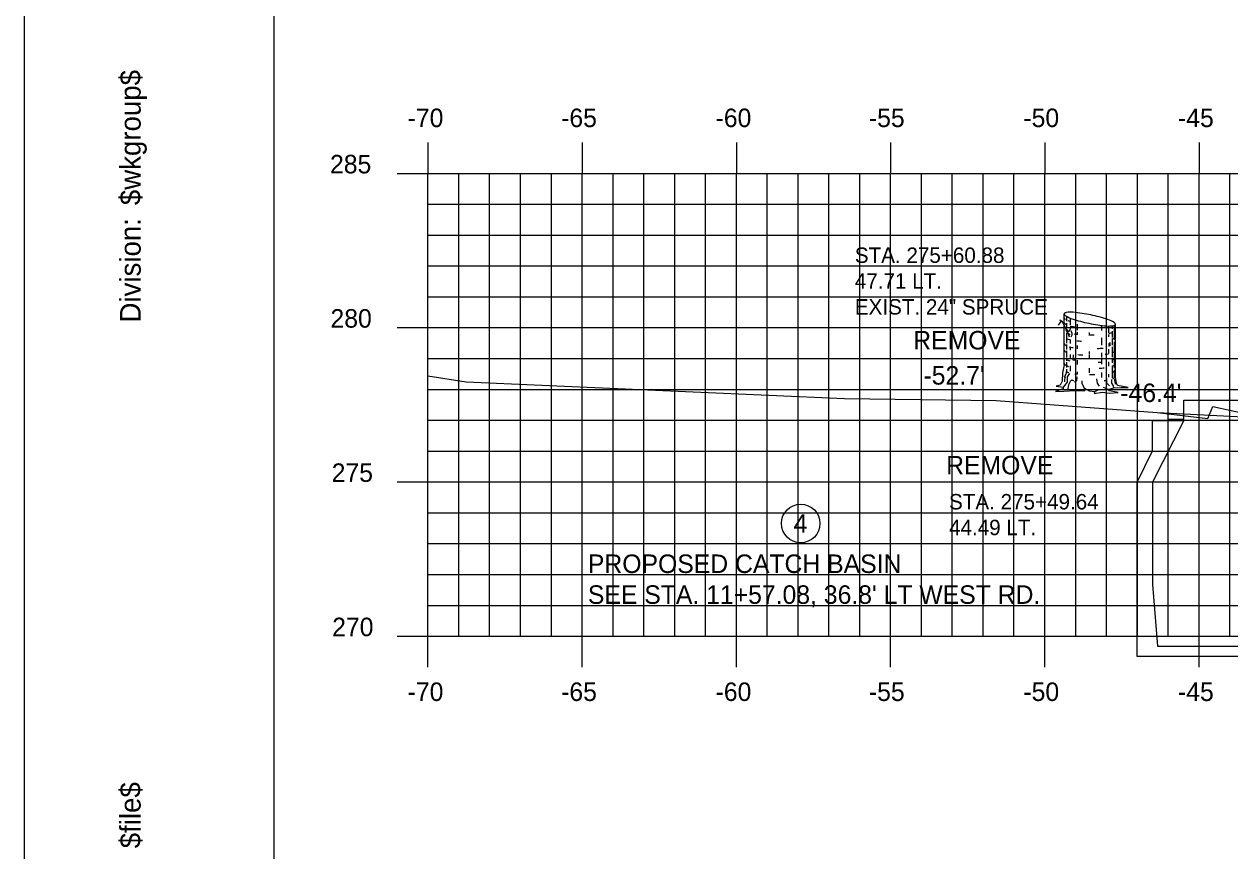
# Model space of a CAD drawing. Extents: x 853563 to 853733, y 366268 to 366378.
# Drawn here: x 853562.67 to 853601.77, y 366295.28 to 366322.07 of the extents above; entities that cross this region are included whole.
import ezdxf

# ---------------------------------------------------------------- set-up
doc = ezdxf.new("R2010")
doc.units = 0
for name, color, linetype in [('ANNOTATION', 7, 'Continuous'), ('BORDER', 7, 'Continuous'), ('D_Drainage_Text', 7, 'Continuous'), ('D_Roadway_FinishedGrade', 7, 'Continuous'), ('D_Text_Monospaced', 7, 'Continuous'), ('D_Text_Standard', 7, 'Continuous'), ('H_V ANNOTATION', 7, 'Continuous'), ('MAJOR', 7, 'Continuous'), ('MINOR', 7, 'Continuous'), ('PLOT BOUNDARY', 7, 'Continuous'), ('S_Drainage_CB', 7, 'Continuous'), ('S_Roadway_Centerline', 7, 'Continuous'), ('S_Trees_Conifer_Pay', 7, 'Continuous')]:
    doc.layers.add(name, color=color, linetype=linetype)

msp = doc.modelspace()

# ---------------------------------------------------------------- linework, layer by layer
at = {"layer": 'BORDER'}
msp.add_line((853570.768, 366376.236), (853570.768, 366271.236), dxfattribs=at)
at = {"layer": 'D_Drainage_Text'}
msp.add_circle((853587.853, 366305.89), 0.625, dxfattribs=at)
at = {"layer": 'D_Roadway_FinishedGrade'}
msp.add_line((853599.411, 366309.486), (853604.283, 366309.236), dxfattribs=at)
at = {"layer": 'MAJOR'}
for p, q in [((853575.768, 366318.238), (853575.768, 366317.236)), ((853580.768, 366318.238), (853580.768, 366317.236)), ((853585.768, 366318.238), (853585.768, 366317.236)), ((853590.768, 366318.238), (853590.768, 366317.236)), ((853595.768, 366318.238), (853595.768, 366317.236)), ((853600.768, 366318.238), (853600.768, 366317.236)), ((853574.766, 366317.236), (853575.768, 366317.236)), ((853575.768, 366317.236), (853715.768, 366317.236)), ((853575.768, 366302.236), (853575.768, 366317.236)), ((853575.768, 366302.236), (853575.768, 366317.236)), ((853575.768, 366317.236), (853715.768, 366317.236)), ((853580.768, 366302.236), (853580.768, 366317.236)), ((853585.768, 366302.236), (853585.768, 366317.236)), ((853590.768, 366302.236), (853590.768, 366317.236)), ((853595.768, 366302.236), (853595.768, 366317.236)), ((853600.768, 366302.236), (853600.768, 366317.236)), ((853574.766, 366312.236), (853575.768, 366312.236)), ((853575.768, 366312.236), (853715.768, 366312.236)), ((853574.766, 366307.236), (853575.768, 366307.236)), ((853575.768, 366307.236), (853715.768, 366307.236)), ((853574.766, 366302.236), (853575.768, 366302.236)), ((853575.768, 366302.236), (853715.768, 366302.236)), ((853575.768, 366302.236), (853715.768, 366302.236)), ((853575.768, 366301.234), (853575.768, 366302.236)), ((853580.768, 366301.234), (853580.768, 366302.236)), ((853585.768, 366301.234), (853585.768, 366302.236)), ((853590.768, 366301.234), (853590.768, 366302.236)), ((853595.768, 366301.234), (853595.768, 366302.236)), ((853600.768, 366301.234), (853600.768, 366302.236))]:
    msp.add_line(p, q, dxfattribs=at)
at = {"layer": 'MINOR'}
for p, q in [((853576.768, 366302.236), (853576.768, 366317.236)), ((853577.768, 366302.236), (853577.768, 366317.236)), ((853578.768, 366302.236), (853578.768, 366317.236)), ((853579.768, 366302.236), (853579.768, 366317.236)), ((853581.768, 366302.236), (853581.768, 366317.236)), ((853582.768, 366302.236), (853582.768, 366317.236)), ((853583.768, 366302.236), (853583.768, 366317.236)), ((853584.768, 366302.236), (853584.768, 366317.236)), ((853586.768, 366302.236), (853586.768, 366317.236)), ((853587.768, 366302.236), (853587.768, 366317.236)), ((853588.768, 366302.236), (853588.768, 366317.236)), ((853589.768, 366302.236), (853589.768, 366317.236)), ((853591.768, 366302.236), (853591.768, 366317.236)), ((853592.768, 366302.236), (853592.768, 366317.236)), ((853593.768, 366302.236), (853593.768, 366317.236)), ((853594.768, 366302.236), (853594.768, 366317.236)), ((853596.768, 366302.236), (853596.768, 366317.236)), ((853597.768, 366302.236), (853597.768, 366317.236)), ((853598.768, 366302.236), (853598.768, 366317.236)), ((853599.768, 366302.236), (853599.768, 366317.236)), ((853601.768, 366302.236), (853601.768, 366317.236)), ((853575.768, 366316.236), (853715.768, 366316.236)), ((853575.768, 366316.236), (853576.77, 366316.236)), ((853575.768, 366315.236), (853715.768, 366315.236)), ((853575.768, 366315.236), (853576.77, 366315.236)), ((853575.768, 366314.236), (853715.768, 366314.236)), ((853575.768, 366314.236), (853576.77, 366314.236)), ((853575.768, 366313.236), (853715.768, 366313.236)), ((853575.768, 366313.236), (853576.77, 366313.236)), ((853575.768, 366311.236), (853715.768, 366311.236)), ((853575.768, 366311.236), (853576.77, 366311.236)), ((853575.768, 366310.236), (853715.768, 366310.236)), ((853575.768, 366310.236), (853576.77, 366310.236)), ((853575.768, 366309.236), (853715.768, 366309.236)), ((853575.768, 366309.236), (853576.77, 366309.236)), ((853575.768, 366308.236), (853715.768, 366308.236)), ((853575.768, 366308.236), (853576.77, 366308.236)), ((853575.768, 366306.236), (853715.768, 366306.236)), ((853575.768, 366306.236), (853576.77, 366306.236)), ((853575.768, 366305.236), (853715.768, 366305.236)), ((853575.768, 366305.236), (853576.77, 366305.236)), ((853575.768, 366304.236), (853715.768, 366304.236)), ((853575.768, 366304.236), (853576.77, 366304.236)), ((853575.768, 366303.236), (853715.768, 366303.236)), ((853575.768, 366303.236), (853576.77, 366303.236))]:
    msp.add_line(p, q, dxfattribs=at)
at = {"layer": 'PLOT BOUNDARY'}
msp.add_lwpolyline([(853562.674, 366268.177), (853732.674, 366268.177), (853732.674, 366378.177), (853562.674, 366378.177)], close=True, dxfattribs=at)
at = {"layer": 'S_Drainage_CB'}
for p, q in [((853599.259, 366308.24), (853599.259, 366309.224)), ((853599.259, 366309.224), (853600.276, 366309.224)), ((853600.276, 366309.224), (853599.259, 366307.223)), ((853598.766, 366307.223), (853599.259, 366308.24)), ((853598.766, 366301.58), (853598.766, 366307.223)), ((853599.259, 366307.223), (853599.259, 366303.909)), ((853599.259, 366303.909), (853599.423, 366301.908)), ((853599.423, 366301.908), (853603.097, 366301.908)), ((853603.753, 366301.58), (853598.766, 366301.58))]:
    msp.add_line(p, q, dxfattribs=at)
msp.add_lwpolyline([(853599.784, 366309.266), (853600.276, 366309.266), (853600.276, 366309.889), (853602.277, 366309.889), (853602.277, 366309.266), (853602.769, 366309.266)], dxfattribs=at)
at = {"layer": 'S_Roadway_Centerline'}
msp.add_lwpolyline([(853575.768, 366310.67), (853577.008, 366310.484), (853589.275, 366309.936), (853594.185, 366309.87), (853599.411, 366309.486), (853601.05, 366309.291), (853601.219, 366309.683), (853603, 366309.295)], dxfattribs=at)
at = {"layer": 'S_Trees_Conifer_Pay'}
for p, q in [((853596.396, 366311.034), (853596.396, 366312.681)), ((853596.467, 366312.609), (853596.467, 366312.446)), ((853596.467, 366312.379), (853596.467, 366312.251)), ((853596.585, 366312.548), (853596.585, 366312.325)), ((853596.585, 366312.236), (853596.585, 366312.189)), ((853596.813, 366312.352), (853596.813, 366312.152)), ((853597.609, 366312.31), (853597.609, 366312.142)), ((853597.829, 366312.289), (853597.829, 366312.057)), ((853597.954, 366312.297), (853597.954, 366312.199)), ((853598.013, 366312.308), (853598.013, 366311.837)), ((853598.06, 366310.624), (853598.06, 366312.346)), ((853596.467, 366312.064), (853596.467, 366311.728)), ((853596.528, 366312.053), (853596.579, 366311.993)), ((853596.585, 366311.854), (853596.585, 366311.722)), ((853596.813, 366312.094), (853596.813, 366312.006)), ((853597.203, 366312.078), (853597.203, 366311.983)), ((853597.609, 366311.905), (853597.609, 366311.668)), ((853597.829, 366312.016), (853597.829, 366311.942)), ((853597.954, 366312.125), (853597.954, 366311.921)), ((853597.954, 366311.863), (853597.954, 366311.664)), ((853598.013, 366311.773), (853598.013, 366311.464)), ((853596.467, 366311.691), (853596.467, 366311.528)), ((853596.467, 366311.481), (853596.467, 366311.264)), ((853596.585, 366311.611), (853596.585, 366311.501)), ((853596.813, 366311.658), (853596.813, 366311.553)), ((853597.203, 366311.464), (853597.203, 366311.39)), ((853597.609, 366311.423), (853597.609, 366311.271)), ((853597.829, 366311.539), (853597.829, 366311.4)), ((853597.954, 366311.617), (853597.954, 366311.281)), ((853598.013, 366311.417), (853598.013, 366310.925)), ((853596.467, 366311.233), (853596.467, 366311.159)), ((853596.467, 366311.119), (853596.467, 366310.945)), ((853596.585, 366311.365), (853596.585, 366311.224)), ((853596.585, 366310.997), (853596.585, 366310.824)), ((853596.813, 366311.186), (853596.813, 366311.04)), ((853597.203, 366311.365), (853597.203, 366311.217)), ((853597.609, 366311.228), (853597.609, 366311.054)), ((853597.829, 366311.129), (853597.829, 366310.987)), ((853597.954, 366311.228), (853597.954, 366311.092)), ((853597.954, 366310.993), (853597.954, 366310.614)), ((853596.813, 366310.808), (853596.813, 366310.719)), ((853597.203, 366310.925), (853597.203, 366310.772)), ((853597.609, 366310.777), (853597.609, 366310.624)), ((853597.829, 366310.725), (853597.829, 366310.63)), ((853598.013, 366310.871), (853598.013, 366310.624)), ((853597.392, 366310.167), (853597.518, 366310.231)), ((853597.829, 366310.231), (853597.666, 366310.295))]:
    msp.add_line(p, q, dxfattribs=at)
for points in [[(853596.35, 366312.412), (853596.274, 366312.42), (853596.202, 366312.321)], [(853596.579, 366312.179), (853596.542, 366312.105), (853596.495, 366312.162), (853596.437, 366312.23), (853596.345, 366312.424), (853596.28, 366312.471), (853596.249, 366312.478)], [(853596.564, 366311.926), (853596.528, 366312.053), (853596.464, 366312.169), (853596.433, 366312.236), (853596.364, 366312.382)], [(853596.612, 366312.142), (853596.643, 366312.057), (853596.647, 366311.989), (853596.616, 366311.926)], [(853597.881, 366311.651), (853597.887, 366311.747), (853597.843, 366311.724), (853597.843, 366311.629)], [(853596.396, 366311.034), (853596.345, 366310.772), (853596.328, 366310.499), (853596.27, 366310.373), (853596.135, 366310.342), (853596.365, 366310.305), (853596.365, 366310.305), (853596.359, 366310.258), (853596.112, 366310.163), (853596.386, 366310.18), (853596.742, 366310.2), (853597.063, 366310.19), (853597.056, 366310.272), (853597.205, 366310.19), (853597.392, 366310.167), (853597.368, 366310.099), (853597.635, 366310.142), (853597.856, 366310.115), (853598.148, 366310.132), (853597.86, 366310.19), (853597.829, 366310.231), (853597.992, 366310.289), (853598.228, 366310.299), (853598.469, 366310.299), (853598.127, 366310.357), (853598.086, 366310.437), (853598.06, 366310.624)], [(853596.742, 366311.253), (853596.729, 366311.176), (853596.682, 366311.186), (853596.694, 366311.353)], [(853596.569, 366310.746), (853596.495, 366310.641), (853596.49, 366310.468), (853596.365, 366310.305)], [(853596.47, 366310.892), (853596.464, 366310.746), (853596.417, 366310.678), (853596.406, 366310.478)], [(853596.806, 366310.641), (853596.795, 366310.515), (853596.721, 366310.472)], [(853596.528, 366310.252), (853596.542, 366310.39), (853596.616, 366310.519)], [(853597.056, 366310.272), (853596.982, 366310.414), (853596.973, 366310.515)], [(853597.545, 366310.342), (853597.477, 366310.437), (853597.45, 366310.577)], [(853597.771, 366310.583), (853597.771, 366310.451), (853597.86, 366310.352)], [(853597.934, 366310.556), (853597.928, 366310.441), (853597.981, 366310.352), (853597.992, 366310.289)], [(853598.012, 366310.577), (853598.033, 366310.499), (853598.053, 366310.404)]]:
    msp.add_lwpolyline(points, dxfattribs=at)
for centre, radius, start, end in [((853596.418, 366312.681), 0.0226, 156.5926, 168.2806), ((853596.418, 366312.681), 0.0226, 168.2806, 179.9685), ((853596.422, 366312.681), 0.0264, 179.9685, 190.7806), ((853596.427, 366312.682), 0.0314, 190.7806, 203.4842), ((853596.422, 366312.68), 0.0264, 145.7806, 156.5926), ((853596.447, 366312.691), 0.0527, 203.4842, 213.2806), ((853596.426, 366312.677), 0.0314, 133.077, 145.7806), ((853596.471, 366312.707), 0.0817, 213.2806, 227.6113), ((853596.44, 366312.661), 0.0527, 123.2806, 133.077), ((853596.456, 366312.637), 0.0817, 108.9499, 123.2806), ((853596.585, 366312.831), 0.251, 227.6113, 235.7806), ((853596.511, 366312.477), 0.251, 100.7806, 108.9499), ((853596.894, 366313.287), 0.802, 235.7806, 251.9406), ((853596.614, 366311.936), 0.802, 84.6206, 100.7806), ((853596.204, 366307.578), 5.179, 78.2806, 84.6206), ((853596.204, 366307.578), 5.179, 71.9406, 78.2806), ((853596.429, 366312.555), 0.0334, 185.7849, 196.0515), ((853596.429, 366312.4), 0.0334, 185.7849, 196.0515), ((853596.439, 366312.558), 0.0441, 196.0515, 210), ((853596.439, 366312.403), 0.0441, 196.0515, 210), ((853596.455, 366312.567), 0.0624, 210, 228.7494), ((853596.455, 366312.412), 0.0624, 210, 228.7494), ((853596.527, 366312.649), 0.172, 228.7494, 240), ((853596.527, 366312.495), 0.172, 228.7494, 240), ((853596.727, 366312.84), 0.571, 240, 242.9763), ((853596.727, 366312.995), 0.571, 247.5868, 255.5683), ((853596.727, 366312.84), 0.571, 255.6333, 261.8968), ((853598.251, 366317.448), 5.179, 251.9406, 258.2806), ((853597.227, 366316.358), 4.124, 261.8968, 263.762), ((853598.251, 366317.448), 5.179, 258.2806, 264.6206), ((853597.227, 366316.358), 4.124, 273.2669, 275.3045), ((853597.841, 366313.091), 0.802, 264.6206, 280.7806), ((853597.561, 366311.74), 0.802, 55.7806, 71.9406), ((853597.944, 366312.549), 0.251, 280.7806, 288.9499), ((853597.871, 366312.195), 0.251, 47.6113, 55.7806), ((853597.999, 366312.39), 0.0817, 288.9499, 303.2806), ((853597.985, 366312.32), 0.0817, 33.2806, 47.6113), ((853598.015, 366312.365), 0.0527, 303.2806, 313.077), ((853598.029, 366312.35), 0.0314, 313.077, 325.7806), ((853598.009, 366312.336), 0.0527, 23.4842, 33.2806), ((853598.034, 366312.347), 0.0264, 325.7806, 336.5926), ((853598.028, 366312.344), 0.0314, 10.7806, 23.4842), ((853598.037, 366312.345), 0.0226, 336.5926, 348.2806), ((853598.033, 366312.345), 0.0264, 359.9685, 10.7806), ((853598.037, 366312.345), 0.0226, 348.2806, 359.9685), ((853598.028, 366312.167), 0.0334, 0, 16.0515), ((853598.028, 366312.167), 0.0334, 343.9485, 360), ((853596.429, 366311.956), 0.0334, 185.7849, 196.0515), ((853596.727, 366312.396), 0.571, 242.9571, 255.5507), ((853597.229, 366316.125), 4.124, 262.9442, 264.2151), ((853597.228, 366315.914), 4.124, 264.0496, 266.2948), ((853597.229, 366316.125), 4.124, 269.6419, 270), ((853597.229, 366316.125), 4.124, 270, 271.9249), ((853597.73, 366312.607), 0.571, 282.0154, 293.1403), ((853597.728, 366312.396), 0.571, 292.9413, 300), ((853597.73, 366312.607), 0.571, 299.6633, 300), ((853597.929, 366312.262), 0.172, 300, 311.2506), ((853598.001, 366312.18), 0.0624, 311.2506, 330), ((853598.017, 366312.17), 0.0441, 330, 343.9485), ((853596.43, 366311.721), 0.0334, 185.7849, 196.0515), ((853596.43, 366311.511), 0.0334, 185.7849, 196.0515), ((853596.441, 366311.724), 0.0441, 196.0515, 210), ((853596.441, 366311.514), 0.0441, 196.0515, 210), ((853596.456, 366311.733), 0.0624, 210, 228.7494), ((853596.456, 366311.523), 0.0624, 210, 228.7494), ((853596.529, 366311.815), 0.172, 228.7494, 240), ((853596.529, 366311.605), 0.172, 228.7494, 240), ((853596.728, 366312.16), 0.571, 240, 242.8104), ((853596.728, 366311.95), 0.571, 240, 242.8104), ((853596.728, 366312.16), 0.571, 253.0704, 261.8968), ((853597.229, 366315.678), 4.124, 261.8968, 262.3875), ((853597.229, 366315.678), 4.124, 273.3324, 275.919), ((853597.229, 366315.468), 4.124, 276.8526, 278.1032), ((853597.73, 366311.95), 0.571, 278.1032, 280.7293), ((853597.73, 366311.95), 0.571, 293.1403, 300), ((853597.73, 366312.16), 0.571, 299.6633, 300), ((853597.929, 366311.815), 0.172, 300, 311.2506), ((853597.929, 366311.605), 0.172, 300, 311.2506), ((853598.001, 366311.733), 0.0624, 311.2506, 330), ((853598.001, 366311.523), 0.0624, 311.2506, 330), ((853598.017, 366311.724), 0.0441, 330, 343.9485), ((853598.017, 366311.514), 0.0441, 330, 343.9485), ((853598.028, 366311.721), 0.0334, 0, 16.0515), ((853598.028, 366311.721), 0.0334, 343.9485, 360), ((853598.028, 366311.511), 0.0334, 0, 16.0515), ((853598.028, 366311.511), 0.0334, 343.9485, 360), ((853596.43, 366311.076), 0.0334, 185.7849, 196.0515), ((853596.441, 366311.079), 0.0441, 196.0515, 210), ((853596.456, 366311.088), 0.0624, 210, 228.7494), ((853596.529, 366311.171), 0.172, 228.7494, 240), ((853596.728, 366311.516), 0.571, 240, 250.7093), ((853596.728, 366311.714), 0.571, 242.8104, 254.6017), ((853597.229, 366315.468), 4.124, 264.5431, 266.8507), ((853597.229, 366315.468), 4.124, 269.6419, 270), ((853597.229, 366315.231), 4.124, 273.6807, 275.284), ((853597.73, 366311.714), 0.571, 293.1403, 300), ((853597.741, 366311.522), 0.571, 291.9732, 298.7631), ((853597.929, 366311.369), 0.172, 300, 311.2506), ((853598.001, 366311.286), 0.0624, 311.2506, 330), ((853598.017, 366311.277), 0.0441, 330, 343.9485), ((853598.028, 366311.274), 0.0334, 0, 16.0515), ((853598.028, 366311.274), 0.0334, 343.9485, 360), ((853598.028, 366311.076), 0.0334, 0, 16.0515), ((853596.43, 366310.66), 0.0334, 185.7849, 196.0515), ((853596.441, 366310.663), 0.0441, 196.0515, 210), ((853596.456, 366310.672), 0.0624, 210, 228.7494), ((853596.529, 366310.755), 0.172, 228.7494, 240), ((853596.728, 366311.32), 0.571, 242.7279, 251.4933), ((853597.229, 366314.838), 4.124, 263.2104, 264.2151), ((853597.229, 366314.838), 4.124, 269.8672, 270), ((853597.229, 366314.838), 4.124, 270, 272.1883), ((853597.229, 366315.034), 4.124, 274.1603, 276.5009), ((853597.73, 366311.32), 0.571, 293.1403, 300), ((853597.73, 366311.1), 0.571, 295.4686, 300), ((853597.929, 366310.975), 0.172, 300, 311.2506), ((853597.929, 366310.755), 0.172, 300, 311.2506), ((853598.001, 366310.893), 0.0624, 311.2506, 330), ((853598.001, 366310.672), 0.0624, 311.2506, 330), ((853598.017, 366310.884), 0.0441, 330, 343.9485), ((853598.017, 366310.663), 0.0441, 330, 343.9485), ((853598.028, 366310.881), 0.0334, 0, 16.0515), ((853598.028, 366310.881), 0.0334, 343.9485, 360), ((853598.028, 366310.66), 0.0334, 0, 16.0515), ((853598.028, 366310.66), 0.0334, 343.9485, 360), ((853596.728, 366311.1), 0.571, 258.363, 261.8968), ((853597.229, 366314.618), 4.124, 261.8968, 262.6316), ((853597.229, 366314.618), 4.124, 276.488, 277.5562)]:
    msp.add_arc(centre, radius, start, end, dxfattribs=at)

# ---------------------------------------------------------------- texts
at = {"layer": 'ANNOTATION'}
for p in [(853591.501, 366311.53), (853592.568, 366307.48)]:
    msp.add_text('REMOVE', height=0.6, dxfattribs=at).set_placement(p)
at = {"layer": 'BORDER'}
for s, p in [('$wkgroup$', (853566.453, 366316.206)), ('Division:', (853566.453, 366312.403)), ('$file$', (853566.453, 366295.362))]:
    msp.add_text(s, height=0.6696, rotation=90, dxfattribs=at).set_placement(p)
at = {"layer": 'D_Drainage_Text'}
for s, p in [('PROPOSED CATCH BASIN', (853580.953, 366304.284)), ("SEE STA. 11+57.08, 36.8' LT WEST RD.", (853580.953, 366303.284))]:
    msp.add_text(s, height=0.6, dxfattribs=at).set_placement(p)
at = {"layer": 'D_Text_Monospaced'}
for s, height, p in [('STA. 275+60.88', 0.49998, (853589.608, 366314.334)), ('47.71 LT.', 0.5, (853589.608, 366313.5)), ('EXIST. 24" SPRUCE', 0.49998, (853589.608, 366312.66)), ('STA. 275+49.64', 0.49998, (853592.662, 366306.344)), ('44.49 LT.', 0.5, (853592.662, 366305.51))]:
    msp.add_text(s, height=height, dxfattribs=at).set_placement(p)
at = {"layer": 'D_Text_Standard'}
for s, p in [("-52.7'", (853591.834, 366310.39)), ("-46.4'", (853598.215, 366309.825))]:
    msp.add_text(s, height=0.6, dxfattribs=at).set_placement(p)
at = {"layer": 'H_V ANNOTATION'}
for s, p in [('-70', (853575.109, 366318.736)), ('-65', (853580.085, 366318.736)), ('-60', (853585.093, 366318.736)), ('-55', (853590.064, 366318.736)), ('-50', (853595.072, 366318.736)), ('-45', (853600.085, 366318.736)), ('285', (853572.592, 366317.236)), ('280', (853572.608, 366312.236)), ('275', (853572.646, 366307.236)), ('4', (853587.622, 366305.586)), ('270', (853572.662, 366302.236)), ('-70', (853575.109, 366300.136)), ('-65', (853580.085, 366300.136)), ('-60', (853585.093, 366300.136)), ('-55', (853590.064, 366300.136)), ('-50', (853595.072, 366300.136)), ('-45', (853600.085, 366300.136))]:
    msp.add_text(s, height=0.6, dxfattribs=at).set_placement(p)
at = {"layer": 'MAJOR'}
msp.add_text('-', height=0.00000006, rotation=53.1301, dxfattribs=at).set_placement((853575.763, 366302.236))

doc.saveas('drawing.dxf')
